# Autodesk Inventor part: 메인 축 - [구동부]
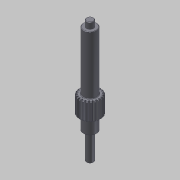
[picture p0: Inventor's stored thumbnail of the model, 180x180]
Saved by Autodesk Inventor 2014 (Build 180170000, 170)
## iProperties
Created: 2016-02
Part Number: 메인 축 - [구동부]
Material: 강철, 연강
Document SubType Name: Modeling
Categories: <?xml version="1.0" encoding="UTF-16"?> <MemberInstance><Categories><FamilyTemplate><FamilyTemplateParameter ValueType="xs:double" Id="1" ObjectReferenceKey="da
Density: 7.86 g/cm^3
Mass: 187.503 g
Surface Area: 82.0529 cm^2
Volume: 23.8554 cm^3
Appearance: 강철
CustomPartVersion: 1
Author: mdu
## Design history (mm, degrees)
sketch "Sketch1"
  geometry: C1 r 12 at (0, 0)
  constraints: 1 centre point
  dimensions: "d0" = 24 diameter of C1 (= da_da)
extrude "Extrusion1" new body sketch "Sketch1" distance "d1" = 20 (= da_b); taper "d2" = 0 deg
workplane "Work Plane2"
feature "피치 지름" dims "d4" = 10, "d5" = 0
workplane "Work Plane8"
workplane "Work Plane9"
chamfer "모따기1" distance "d49" = 1; stored, may be unused: second distance "d50" = 2, angle "d51" = 45 deg
sketch "스케치3"
  geometry: C1 r 7.5 at (0, 0); 1 further point
  constraints: 1 centre point, 1 coincident
  dimensions: "d52" = 15 diameter of C1
extrude "돌출2" join sketch "스케치3" distance "d53" = 66; taper "d54" = 0 deg
sketch "스케치4"
  geometry: C1 r 4 at (0, 0); 1 further point
  constraints: 1 centre point, 1 coincident
  dimensions: "d55" = 8 diameter of C1
extrude "돌출3" join sketch "스케치4" distance "d56" = 7; taper "d57" = 0 deg
sketch "스케치5"
  geometry: C1 r 7.5 at (0, 0) reference; C2 r 7.5 at (0, 0) reference; 1 further point
extrude "돌출4" join sketch "스케치5" distance "d62" = 16; taper "d63" = 0 deg
sketch "스케치6"
  geometry: C1 r 4 at (0, 0); 1 further point
  constraints: 1 centre point, 1 coincident
  dimensions: "d64" = 8 diameter of C1
extrude "돌출5" join sketch "스케치6" distance "d65" = 30; taper "d66" = 0 deg
chamfer "모따기2" distance "d58" = 0.5; stored, may be unused: second distance "d59" = 2, angle "d60" = 45 deg
fillet "모깎기1" dims "d61" = 0.5
feature "스퍼 기어" dims "da_b" = 20, "da_d" = 22, "da_aw" = 31, "da_da" = 24, "da_df" = 19.5, "da_dw" = 22, angle "da_beta" = 0 deg, "da_lefttooth" = 0, "da_righttooth" = 0
sketch "스케치7" dims "d68" = 18
  geometry: C1 r 0.25 at (0, -9); 2 further points
  constraints: 2 vertical alignment, 1 centre point, 1 coincident, 2 other
  dimensions: "d67" = 0.5 diameter of C1
extrude "돌출6" join sketch "스케치7" distance "d69" = 0.3; taper "d70" = 0 deg
body "Solid1"
sketch "Sketch2"
  geometry: C1 r 12 at (0, 0) reference; C2 r 11 at (0, 0)
  constraints: 1 centre point, 1 coincident
  dimensions: "d3" = 22 diameter of C2 (= da_dw)
body "Srf1"
node "투영된 루프1"
other parameters: "d16" = 31 (= da_aw), "d17" = 0, "d34" = 1.428 (computed from da_z), "d39" = 0, "d41" = 0, "d43" = 31 (= da_aw), "d46" = 31 (= da_aw), "d47" = 0, "d48" = 0
